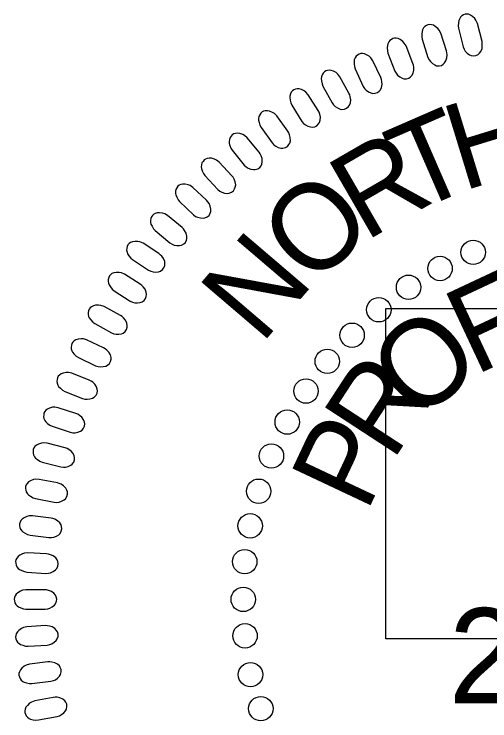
# Model space of a CAD drawing. Extents: x 18938 to 19565, y 6931 to 7973.
# Drawn here: x 19354.83 to 19358.89, y 7943.91 to 7949.93 of the extents above; entities that cross this region are included whole.
import ezdxf

# ---------------------------------------------------------------- set-up
doc = ezdxf.new("R2010")
doc.units = 0
for name, color, linetype in [('Old_Level_10', 7, 'Continuous'), ('Prop Pavement Schedule Description CELL', 7, 'Continuous'), ('Scratch_Level_5', 7, 'Continuous')]:
    doc.layers.add(name, color=color, linetype=linetype)

# ---------------------------------------------------------------- blocks, each defined once
blk = doc.blocks.new('Brandon J. McInnis')
at = {"layer": 'Old_Level_10'}
for points in [[(-60.071, 87.604), (-60.375, 88.792), (-60.466, 88.995), (-60.552, 89.118), (-60.702, 89.254), (-60.824, 89.336), (-60.952, 89.386), (-61.064, 89.399), (-61.177, 89.39), (-61.281, 89.343), (-61.389, 89.284), (-61.476, 89.2), (-61.552, 89.077), (-61.591, 88.986), (-61.619, 88.823), (-61.632, 88.635), (-61.614, 88.475), (-61.309, 87.256), (-61.245, 87.097), (-61.167, 86.973), (-61.04, 86.841), (-60.897, 86.733), (-60.783, 86.681), (-60.616, 86.661), (-60.466, 86.679), (-60.331, 86.754), (-60.243, 86.829), (-60.144, 86.957), (-60.071, 87.151), (-60.05, 87.342), (-60.053, 87.474)], [(-62.405, 86.983), (-62.783, 88.15), (-62.886, 88.347), (-62.979, 88.464), (-63.138, 88.591), (-63.264, 88.665), (-63.396, 88.706), (-63.508, 88.712), (-63.62, 88.696), (-63.721, 88.643), (-63.825, 88.577), (-63.906, 88.489), (-63.975, 88.361), (-64.008, 88.266), (-64.026, 88.103), (-64.027, 87.914), (-63.999, 87.755), (-63.618, 86.558), (-63.544, 86.404), (-63.459, 86.285), (-63.324, 86.161), (-63.175, 86.063), (-63.058, 86.017), (-62.889, 86.008), (-62.741, 86.035), (-62.611, 86.119), (-62.527, 86.199), (-62.437, 86.333), (-62.376, 86.532), (-62.367, 86.723), (-62.379, 86.856)], [(-64.605, 86.167), (-65.057, 87.308), (-65.172, 87.498), (-65.272, 87.609), (-65.439, 87.725), (-65.569, 87.791), (-65.703, 87.824), (-65.815, 87.823), (-65.926, 87.8), (-66.023, 87.74), (-66.124, 87.668), (-66.199, 87.574), (-66.26, 87.443), (-66.286, 87.347), (-66.294, 87.183), (-66.283, 86.994), (-66.245, 86.838), (-65.79, 85.666), (-65.707, 85.517), (-65.614, 85.404), (-65.471, 85.288), (-65.316, 85.2), (-65.196, 85.161), (-65.028, 85.163), (-64.882, 85.2), (-64.758, 85.292), (-64.679, 85.377), (-64.597, 85.516), (-64.548, 85.718), (-64.552, 85.91), (-64.572, 86.041)], [(-66.723, 85.234), (-67.245, 86.344), (-67.372, 86.526), (-67.479, 86.631), (-67.652, 86.737), (-67.787, 86.794), (-67.922, 86.819), (-68.034, 86.811), (-68.144, 86.781), (-68.237, 86.715), (-68.332, 86.638), (-68.402, 86.539), (-68.454, 86.404), (-68.474, 86.306), (-68.472, 86.142), (-68.449, 85.954), (-68.402, 85.8), (-67.873, 84.661), (-67.781, 84.516), (-67.681, 84.409), (-67.532, 84.303), (-67.371, 84.224), (-67.25, 84.193), (-67.082, 84.206), (-66.938, 84.251), (-66.82, 84.351), (-66.746, 84.441), (-66.674, 84.585), (-66.637, 84.789), (-66.653, 84.98), (-66.681, 85.111)], [(-68.806, 84.22), (-69.397, 85.295), (-69.535, 85.47), (-69.648, 85.567), (-69.828, 85.662), (-69.966, 85.711), (-70.102, 85.727), (-70.213, 85.711), (-70.321, 85.675), (-70.41, 85.604), (-70.501, 85.52), (-70.563, 85.417), (-70.607, 85.279), (-70.621, 85.18), (-70.608, 85.017), (-70.574, 84.83), (-70.517, 84.68), (-69.918, 83.575), (-69.817, 83.437), (-69.71, 83.337), (-69.556, 83.24), (-69.389, 83.171), (-69.266, 83.148), (-69.099, 83.171), (-68.959, 83.226), (-68.847, 83.333), (-68.779, 83.427), (-68.716, 83.576), (-68.693, 83.782), (-68.72, 83.972), (-68.757, 84.099)], [(-70.823, 83.078), (-71.48, 84.114), (-71.63, 84.28), (-71.748, 84.369), (-71.933, 84.453), (-72.074, 84.493), (-72.211, 84.5), (-72.322, 84.478), (-72.427, 84.435), (-72.511, 84.358), (-72.596, 84.269), (-72.652, 84.162), (-72.687, 84.022), (-72.695, 83.923), (-72.672, 83.76), (-72.626, 83.577), (-72.56, 83.429), (-71.893, 82.364), (-71.783, 82.233), (-71.67, 82.139), (-71.509, 82.053), (-71.34, 81.995), (-71.215, 81.979), (-71.05, 82.013), (-70.914, 82.076), (-70.809, 82.19), (-70.747, 82.288), (-70.693, 82.44), (-70.683, 82.648), (-70.723, 82.836), (-70.766, 82.96)], [(-72.824, 81.723), (-73.545, 82.716), (-73.704, 82.872), (-73.828, 82.954), (-74.019, 83.026), (-74.162, 83.057), (-74.299, 83.056), (-74.408, 83.027), (-74.51, 82.977), (-74.589, 82.895), (-74.668, 82.801), (-74.717, 82.691), (-74.744, 82.548), (-74.745, 82.449), (-74.712, 82.288), (-74.655, 82.107), (-74.579, 81.965), (-73.847, 80.944), (-73.729, 80.82), (-73.611, 80.733), (-73.445, 80.657), (-73.272, 80.61), (-73.146, 80.602), (-72.984, 80.646), (-72.851, 80.718), (-72.754, 80.838), (-72.699, 80.939), (-72.654, 81.095), (-72.657, 81.303), (-72.708, 81.488), (-72.76, 81.61)], [(-74.704, 80.335), (-75.486, 81.28), (-75.655, 81.425), (-75.784, 81.5), (-75.978, 81.559), (-76.123, 81.582), (-76.26, 81.572), (-76.366, 81.535), (-76.465, 81.479), (-76.539, 81.392), (-76.612, 81.293), (-76.655, 81.181), (-76.672, 81.037), (-76.667, 80.937), (-76.624, 80.779), (-76.556, 80.603), (-76.471, 80.465), (-75.677, 79.492), (-75.551, 79.376), (-75.427, 79.297), (-75.257, 79.231), (-75.081, 79.195), (-74.955, 79.195), (-74.796, 79.249), (-74.668, 79.329), (-74.579, 79.455), (-74.53, 79.56), (-74.495, 79.718), (-74.512, 79.925), (-74.574, 80.106), (-74.634, 80.225)], [(-76.492, 78.795), (-77.331, 79.69), (-77.509, 79.825), (-77.643, 79.891), (-77.841, 79.938), (-77.986, 79.951), (-78.123, 79.933), (-78.226, 79.89), (-78.322, 79.828), (-78.39, 79.736), (-78.457, 79.632), (-78.492, 79.518), (-78.5, 79.373), (-78.489, 79.274), (-78.436, 79.119), (-78.356, 78.947), (-78.264, 78.816), (-77.409, 77.894), (-77.277, 77.786), (-77.149, 77.715), (-76.974, 77.66), (-76.796, 77.634), (-76.671, 77.642), (-76.516, 77.707), (-76.393, 77.795), (-76.312, 77.926), (-76.269, 78.034), (-76.244, 78.193), (-76.273, 78.399), (-76.348, 78.576), (-76.414, 78.691)], [(-78.154, 77.186), (-79.048, 78.026), (-79.234, 78.149), (-79.371, 78.207), (-79.572, 78.241), (-79.718, 78.246), (-79.853, 78.218), (-79.954, 78.169), (-80.045, 78.101), (-80.107, 78.006), (-80.167, 77.898), (-80.196, 77.782), (-80.195, 77.637), (-80.177, 77.538), (-80.115, 77.387), (-80.025, 77.22), (-79.924, 77.094), (-79.013, 76.229), (-78.874, 76.129), (-78.742, 76.066), (-78.564, 76.022), (-78.386, 76.009), (-78.261, 76.024), (-78.11, 76.098), (-77.993, 76.193), (-77.92, 76.33), (-77.884, 76.44), (-77.87, 76.601), (-77.911, 76.804), (-77.996, 76.976), (-78.07, 77.086)], [(-79.768, 75.399), (-80.712, 76.182), (-80.906, 76.293), (-81.046, 76.342), (-81.249, 76.363), (-81.395, 76.358), (-81.527, 76.323), (-81.625, 76.268), (-81.712, 76.194), (-81.768, 76.095), (-81.821, 75.983), (-81.843, 75.865), (-81.832, 75.721), (-81.809, 75.624), (-81.736, 75.477), (-81.636, 75.315), (-81.528, 75.197), (-80.565, 74.39), (-80.42, 74.299), (-80.284, 74.245), (-80.103, 74.212), (-79.925, 74.209), (-79.801, 74.234), (-79.655, 74.316), (-79.544, 74.418), (-79.479, 74.559), (-79.451, 74.671), (-79.447, 74.833), (-79.501, 75.033), (-79.596, 75.2), (-79.678, 75.305)], [(-81.292, 73.697), (-82.322, 74.363), (-82.527, 74.45), (-82.673, 74.483), (-82.876, 74.48), (-83.021, 74.458), (-83.148, 74.407), (-83.239, 74.341), (-83.317, 74.257), (-83.361, 74.153), (-83.4, 74.036), (-83.407, 73.916), (-83.38, 73.774), (-83.346, 73.68), (-83.256, 73.542), (-83.138, 73.394), (-83.016, 73.289), (-81.965, 72.601), (-81.81, 72.528), (-81.669, 72.49), (-81.486, 72.478), (-81.308, 72.497), (-81.188, 72.536), (-81.053, 72.635), (-80.955, 72.749), (-80.907, 72.897), (-80.892, 73.011), (-80.907, 73.172), (-80.984, 73.365), (-81.099, 73.519), (-81.192, 73.614)], [(-82.507, 71.674), (-83.542, 72.332), (-83.747, 72.418), (-83.893, 72.449), (-84.097, 72.446), (-84.241, 72.422), (-84.369, 72.37), (-84.458, 72.303), (-84.536, 72.219), (-84.579, 72.113), (-84.617, 71.997), (-84.623, 71.876), (-84.595, 71.735), (-84.56, 71.641), (-84.469, 71.504), (-84.35, 71.357), (-84.228, 71.253), (-83.17, 70.573), (-83.015, 70.501), (-82.873, 70.464), (-82.691, 70.454), (-82.513, 70.474), (-82.393, 70.513), (-82.259, 70.614), (-82.162, 70.73), (-82.115, 70.877), (-82.101, 70.992), (-82.117, 71.153), (-82.196, 71.344), (-82.312, 71.497), (-82.405, 71.593)], [(-83.81, 69.625), (-84.885, 70.217), (-85.095, 70.29), (-85.243, 70.311), (-85.445, 70.295), (-85.589, 70.262), (-85.712, 70.203), (-85.797, 70.13), (-85.869, 70.042), (-85.905, 69.934), (-85.937, 69.815), (-85.935, 69.694), (-85.898, 69.554), (-85.857, 69.464), (-85.759, 69.332), (-85.63, 69.193), (-85.501, 69.097), (-84.404, 68.485), (-84.245, 68.422), (-84.101, 68.395), (-83.918, 68.396), (-83.741, 68.427), (-83.624, 68.474), (-83.496, 68.582), (-83.407, 68.704), (-83.37, 68.854), (-83.363, 68.969), (-83.389, 69.129), (-83.48, 69.315), (-83.605, 69.461), (-83.704, 69.55)], [(-84.919, 67.501), (-86.029, 68.024), (-86.243, 68.084), (-86.392, 68.096), (-86.593, 68.067), (-86.734, 68.026), (-86.853, 67.958), (-86.934, 67.88), (-87, 67.787), (-87.03, 67.678), (-87.053, 67.556), (-87.044, 67.437), (-86.999, 67.3), (-86.952, 67.212), (-86.845, 67.087), (-86.708, 66.956), (-86.574, 66.867), (-85.439, 66.325), (-85.277, 66.274), (-85.131, 66.255), (-84.949, 66.268), (-84.775, 66.31), (-84.661, 66.364), (-84.54, 66.48), (-84.458, 66.607), (-84.431, 66.759), (-84.431, 66.876), (-84.467, 67.033), (-84.57, 67.213), (-84.703, 67.35), (-84.808, 67.433)], [(-85.858, 65.383), (-86.998, 65.834), (-87.216, 65.88), (-87.365, 65.884), (-87.565, 65.842), (-87.702, 65.792), (-87.817, 65.717), (-87.893, 65.634), (-87.953, 65.537), (-87.976, 65.426), (-87.992, 65.303), (-87.975, 65.184), (-87.921, 65.05), (-87.869, 64.965), (-87.754, 64.847), (-87.609, 64.726), (-87.47, 64.646), (-86.304, 64.176), (-86.139, 64.135), (-85.992, 64.125), (-85.811, 64.149), (-85.64, 64.202), (-85.529, 64.263), (-85.415, 64.387), (-85.343, 64.518), (-85.324, 64.672), (-85.332, 64.788), (-85.378, 64.943), (-85.492, 65.116), (-85.634, 65.245), (-85.744, 65.321)], [(-86.734, 63.193), (-87.901, 63.572), (-88.121, 63.605), (-88.27, 63.599), (-88.466, 63.545), (-88.601, 63.486), (-88.711, 63.404), (-88.781, 63.317), (-88.834, 63.216), (-88.85, 63.103), (-88.859, 62.98), (-88.834, 62.863), (-88.772, 62.732), (-88.714, 62.65), (-88.593, 62.54), (-88.441, 62.428), (-88.296, 62.357), (-87.103, 61.961), (-86.935, 61.93), (-86.788, 61.93), (-86.609, 61.966), (-86.442, 62.029), (-86.335, 62.097), (-86.23, 62.227), (-86.165, 62.363), (-86.157, 62.518), (-86.172, 62.633), (-86.227, 62.785), (-86.351, 62.951), (-86.502, 63.07), (-86.616, 63.139)], [(-87.438, 60.938), (-88.627, 61.243), (-88.848, 61.261), (-88.997, 61.246), (-89.189, 61.179), (-89.319, 61.113), (-89.425, 61.024), (-89.489, 60.932), (-89.537, 60.829), (-89.545, 60.716), (-89.546, 60.592), (-89.514, 60.475), (-89.444, 60.35), (-89.381, 60.272), (-89.253, 60.169), (-89.094, 60.067), (-88.945, 60.005), (-87.73, 59.685), (-87.56, 59.665), (-87.414, 59.673), (-87.237, 59.721), (-87.074, 59.794), (-86.972, 59.868), (-86.875, 60.006), (-86.819, 60.146), (-86.82, 60.3), (-86.842, 60.414), (-86.907, 60.562), (-87.041, 60.72), (-87.199, 60.83), (-87.317, 60.891)], [(-87.95, 58.642), (-89.154, 58.872), (-89.377, 58.877), (-89.524, 58.852), (-89.712, 58.773), (-89.838, 58.699), (-89.937, 58.603), (-89.996, 58.508), (-90.037, 58.402), (-90.038, 58.288), (-90.031, 58.165), (-89.992, 58.051), (-89.914, 57.929), (-89.847, 57.856), (-89.712, 57.761), (-89.547, 57.669), (-89.395, 57.617), (-88.161, 57.373), (-87.991, 57.364), (-87.845, 57.382), (-87.672, 57.44), (-87.514, 57.524), (-87.417, 57.604), (-87.329, 57.747), (-87.281, 57.891), (-87.292, 58.045), (-87.322, 58.157), (-87.396, 58.301), (-87.539, 58.45), (-87.704, 58.55), (-87.826, 58.603)], [(-88.37, 56.328), (-89.587, 56.482), (-89.809, 56.472), (-89.955, 56.438), (-90.137, 56.348), (-90.258, 56.266), (-90.351, 56.164), (-90.404, 56.066), (-90.438, 55.957), (-90.432, 55.843), (-90.417, 55.72), (-90.371, 55.609), (-90.285, 55.493), (-90.214, 55.424), (-90.074, 55.338), (-89.903, 55.256), (-89.748, 55.214), (-88.502, 55.048), (-88.331, 55.05), (-88.187, 55.077), (-88.018, 55.145), (-87.865, 55.239), (-87.774, 55.326), (-87.694, 55.474), (-87.655, 55.62), (-87.677, 55.773), (-87.713, 55.883), (-87.796, 56.022), (-87.949, 56.161), (-88.119, 56.251), (-88.243, 56.297)], [(-88.656, 53.984), (-89.881, 54.061), (-90.102, 54.038), (-90.245, 53.994), (-90.421, 53.893), (-90.537, 53.803), (-90.624, 53.696), (-90.67, 53.594), (-90.697, 53.484), (-90.684, 53.371), (-90.661, 53.249), (-90.609, 53.141), (-90.516, 53.031), (-90.44, 52.966), (-90.295, 52.889), (-90.12, 52.818), (-89.962, 52.786), (-88.708, 52.699), (-88.537, 52.71), (-88.395, 52.746), (-88.23, 52.826), (-88.084, 52.929), (-87.998, 53.021), (-87.929, 53.174), (-87.899, 53.322), (-87.93, 53.473), (-87.973, 53.581), (-88.064, 53.714), (-88.226, 53.844), (-88.401, 53.923), (-88.528, 53.96)], [(-88.787, 51.633), (-90.013, 51.633), (-90.233, 51.595), (-90.373, 51.544), (-90.542, 51.432), (-90.652, 51.334), (-90.731, 51.222), (-90.771, 51.118), (-90.792, 51.005), (-90.771, 50.894), (-90.742, 50.774), (-90.682, 50.669), (-90.582, 50.565), (-90.503, 50.505), (-90.353, 50.437), (-90.173, 50.378), (-90.014, 50.355), (-88.757, 50.347), (-88.588, 50.369), (-88.448, 50.415), (-88.289, 50.504), (-88.149, 50.616), (-88.069, 50.713), (-88.009, 50.87), (-87.989, 51.02), (-88.029, 51.169), (-88.079, 51.274), (-88.178, 51.401), (-88.348, 51.521), (-88.527, 51.588), (-88.657, 51.618)], [(-88.734, 49.275), (-89.959, 49.199), (-90.175, 49.148), (-90.311, 49.087), (-90.474, 48.964), (-90.578, 48.86), (-90.65, 48.743), (-90.683, 48.637), (-90.696, 48.523), (-90.669, 48.413), (-90.631, 48.295), (-90.566, 48.195), (-90.459, 48.096), (-90.376, 48.042), (-90.222, 47.984), (-90.039, 47.936), (-89.879, 47.923), (-88.624, 47.994), (-88.456, 48.027), (-88.32, 48.081), (-88.166, 48.181), (-88.034, 48.301), (-87.96, 48.402), (-87.91, 48.563), (-87.9, 48.713), (-87.949, 48.86), (-88.005, 48.962), (-88.113, 49.082), (-88.289, 49.191), (-88.473, 49.247), (-88.604, 49.269)], [(-88.569, 46.894), (-89.787, 46.741), (-89.999, 46.676), (-90.132, 46.607), (-90.286, 46.475), (-90.383, 46.364), (-90.448, 46.243), (-90.474, 46.134), (-90.48, 46.02), (-90.446, 45.912), (-90.402, 45.797), (-90.33, 45.7), (-90.217, 45.609), (-90.13, 45.56), (-89.974, 45.512), (-89.788, 45.475), (-89.627, 45.473), (-88.379, 45.622), (-88.214, 45.665), (-88.081, 45.728), (-87.934, 45.836), (-87.809, 45.965), (-87.742, 46.071), (-87.702, 46.235), (-87.702, 46.386), (-87.76, 46.529), (-87.822, 46.627), (-87.937, 46.741), (-88.12, 46.838), (-88.307, 46.882), (-88.439, 46.895)], [(-88.236, 44.569), (-89.441, 44.339), (-89.65, 44.261), (-89.777, 44.185), (-89.923, 44.042), (-90.013, 43.926), (-90.07, 43.801), (-90.089, 43.691), (-90.088, 43.577), (-90.047, 43.471), (-89.995, 43.359), (-89.918, 43.267), (-89.8, 43.183), (-89.71, 43.139), (-89.55, 43.101), (-89.363, 43.076), (-89.202, 43.083), (-87.966, 43.311), (-87.804, 43.365), (-87.675, 43.435), (-87.536, 43.553), (-87.419, 43.69), (-87.359, 43.8), (-87.33, 43.965), (-87.338, 44.116), (-87.405, 44.255), (-87.473, 44.349), (-87.595, 44.455), (-87.784, 44.541), (-87.974, 44.573), (-88.106, 44.578)]]:
    blk.add_lwpolyline(points, close=True, dxfattribs=at)
for centre in [(-60.65, 73.77), (-62.825, 72.709), (-64.895, 71.475), (-66.847, 70.001), (-68.599, 68.329), (-70.232, 66.616), (-71.626, 64.665), (-72.861, 62.633), (-73.897, 60.403), (-74.734, 58.093), (-75.292, 55.822), (-75.651, 53.472), (-75.748, 50.997), (-75.629, 48.607), (-75.271, 46.057), (-74.595, 43.826)]:
    blk.add_circle(centre, 0.801, dxfattribs=at)
for s, height, rotation, p in [('H', 5.669, 17.0557, (-61.361, 77.767)), ('T', 5.669, 23.5451, (-64.54, 76.357)), ('R', 5.669, 30.0345, (-67.761, 74.438)), ('O', 5.669, 43.0132, (-71.236, 71.41)), ('N', 5.669, 49.5025, (-74.583, 67.655)), ('F', 5.669, 25.1084, (-60.555, 65.659)), ('O', 5.669, 40.988, (-64.252, 62.521)), ('R', 5.669, 56.8676, (-65.966, 59.974)), ('P', 5.669, 64.8074, (-67.652, 56.612)), ('29470', 6.2363, 359.9814, (-62.253, 44.185))]:
    blk.add_text(s, height=height, rotation=rotation, dxfattribs=at).set_placement(p)

msp = doc.modelspace()

# ---------------------------------------------------------------- linework, layer by layer
at = {"layer": 'Scratch_Level_5'}
msp.add_lwpolyline([(19358.0043, 7944.6047), (19358.0043, 7947.4247), (19375.6443, 7947.4247), (19375.6443, 7944.6047)], close=True, dxfattribs=at)

# ---------------------------------------------------------------- block references
at = {"layer": 'Prop Pavement Schedule Description CELL', "xscale": 0.13, "yscale": 0.13}
msp.add_blockref('Brandon J. McInnis', (19366.6353, 7938.3131), dxfattribs=at)

doc.saveas('drawing.dxf')
